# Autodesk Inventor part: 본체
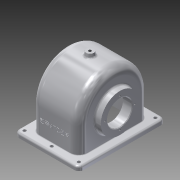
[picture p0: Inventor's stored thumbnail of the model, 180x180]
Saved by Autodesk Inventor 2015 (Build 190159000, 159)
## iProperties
Created: 2015-09
Part Number: 본체
Material: 알루미늄 6061
Document SubType Name: Modeling
Designer: PHO-1
Density: 2.7 g/cm^3
Appearance: 알루미늄 - 평지
Mass: 667.995 g
Surface Area: 883.587 cm^2
Volume: 247.405 cm^3
Author: PHO-1
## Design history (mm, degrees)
sketch "스케치2"
  geometry: L1 (-45, -70)-(45, -70); L2 (52, -63)-(52, 63); L3 (45, 70)-(-45, 70); L4 (-52, 63)-(-52, -63); L5 (-52, -70)-(52, 70); L6 (52, -70)-(-52, 70); A1 r 7 centre (-45, 63) between (-45, 70) and (-52, 63); A2 r 7 centre (45, 63) between (52, 63) and (45, 70); A3 r 7 centre (45, -63) between (45, -70) and (52, -63); A4 r 7 centre (-45, -63) between (-52, -63) and (-45, -70); 1 further point
  constraints: 12 end point, 8 point on circle, 8 point on line, 8 tangent, 4 centre point, 3 equal radius, 2 midpoint, 2 parallel, 1 horizontal, 1 perpendicular
  dimensions: "d2" = 7 radius of A1
extrude "돌출1" new body sketch "스케치2" distance "d3" = 7; taper "d4" = 0 deg
sketch "스케치3"
  geometry: L1 (44, -62)-(-44, -62); L2 (-44, -62)-(-44, 62); L3 (-44, 62)-(44, 62); L4 (44, 62)-(44, -62); 7 further points
  constraints: 8 end point, 4 coincident, 2 midpoint, 2 parallel, 1 horizontal, 1 perpendicular
  dimensions: "d5" = 88 distance of L2.end L3.end; "d6" = 124 distance of L1.end L2.end
hole "구멍1" sketch "스케치3" at (-44, 62), (0, 62), (44, 62), (44, -62), (0, -62), (-44, -62) diameter "d7" = 5; stored, may be unused: countersink angle "d11" = 90 deg, drill point angle "d13" = 0 deg; dims "d8" = 6, "d9" = 4, "d10" = 2, "d12" = 8
sketch "스케치4"
  geometry: L1 (59.5, 7)-(59.5, 0) reference; L2 (59.5, 0)-(-59.5, 0) reference; L3 (-59.5, 0)-(-59.5, 7) reference; L4 (-59.5, 7)-(59.5, 7) reference; L5 (-70, 0)-(-70, 7) reference; L6 (-70, 7)-(-64.5, 7) reference; L7 (-64.5, 7)-(-64.5, 0) reference; L8 (-64.5, 0)-(-70, 0) reference; L9 (70, 7)-(70, 0) reference; L10 (70, 0)-(64.5, 0) reference; L11 (64.5, 0)-(64.5, 7) reference; L12 (64.5, 7)-(70, 7) reference; L13 (57, 47)-(57, 7); L14 (-57, 7)-(-57, 47); A1 r 57 centre (0, 47) between (57, 47) and (-57, 47)
  constraints: 4 end point, 2 point on circle, 2 point on line, 1 centre point, 1 parallel
  dimensions: "d94" = 57 radius of A1
extrude "돌출2" join sketch "스케치4" stored distance "d19" = 77; taper "d20" = 0 deg
sketch "스케치5"
  geometry: L1 (59.5, 7)-(59.5, 0) reference; L2 (59.5, 0)-(-59.5, 0) reference; L3 (-59.5, 0)-(-59.5, 7) reference; L4 (-59.5, 7)-(-57, 7) reference; L5 (-57, 7)-(-57, 47) reference; L6 (57, 47)-(57, 7) reference; L7 (57, 7)-(59.5, 7) reference; L8 (-70, 0)-(-70, 7) reference; L9 (-70, 7)-(-64.5, 7) reference; L10 (-64.5, 7)-(-64.5, 0) reference; L11 (-64.5, 0)-(-70, 0) reference; L12 (70, 7)-(70, 0) reference; L13 (70, 0)-(64.5, 0) reference; L14 (64.5, 0)-(64.5, 7) reference; L15 (64.5, 7)-(70, 7) reference; L16 (-51, 47)-(-51, 0); L17 (51, 0)-(51, 47); A1 r 57 centre (0, 47) between (57, 47) and (-57, 47) reference; A2 r 51 centre (0, 47) between (51, 47) and (-51, 47); 1 further point
  constraints: 4 end point, 2 point on circle, 2 point on line, 1 centre point
  dimensions: "d21" = 6 radial gap between concentric circles of A1 A2
extrude "돌출3" cut sketch "스케치5" stored distance "d22" = 67; taper "d23" = 0 deg
sketch "스케치6"
  geometry: C1 r 31 at (-47, 0); 2 further points
  constraints: 1 centre point, 1 coincident
  dimensions: "d24" = 62 diameter of C1
extrude "돌출4" join sketch "스케치6" distance "d25" = 10; taper "d26" = 0 deg
node "작업 평면1"
sketch "스케치8"
  geometry: C1 r 28 at (-47, 0); 2 further points
  constraints: 1 centre point, 1 coincident
  dimensions: "d28" = 28 radius of C1
extrude "돌출5" join sketch "스케치8" stored distance "d29" = 10; taper "d30" = 40 deg
sketch "스케치10"
  geometry: L1 (38.5, 84.416)-(24.5, 72.668); L2 (24.5, 72.668)-(24.5, 47); L3 (38.5, 47)-(38.5, 84.416); L4 (38.5, 47)-(24.5, 47); 1 further point
  constraints: 8 end point, 1 point on line
revolve "회전1" sketch "스케치10" stored, may be unused: angle "d33" = 90 deg
sketch "스케치12"
  geometry: L1 (33.5, 47)-(-33.5, 47) reference; L2 (19.5, 47)-(35.5, 47); L3 (35.5, 47)-(35.5, 80); L4 (19.5, 75)-(19.5, 47); L5 (35.5, 80)-(33.237, 80); L6 (19.5, 75)-(33.237, 80); 1 further point
  constraints: 10 end point, 2 parallel, 1 horizontal, 1 perpendicular, 1 point on line
  dimensions: "d37" = 33 distance of L3.end L2.end
revolve "회전2" sketch "스케치12" stored, may be unused: angle "d38" = 90 deg
node "작업 평면4"
  node "작업 평면3"
sketch "스케치14"
  geometry: C1 r 6 at (0, 0); 1 further point
  constraints: 1 centre point, 1 coincident
  dimensions: "d40" = 6 radius of C1
extrude "돌출6" join sketch "스케치14" stored distance "d41" = 10; taper "d42" = 10 deg
sketch "스케치16"
  geometry: 2 further points
  constraints: 1 coincident
hole "구멍2" sketch "스케치16" at (0, 0) diameter "d43" = 4.459; stored, may be unused: countersink angle "d47" = 90 deg, drill point angle "d49" = 0 deg; dims "d44" = 15, "d45" = 4, "d46" = 2, "d48" = 12.8
sketch "스케치17"
  geometry: 2 further points
hole "구멍3" sketch "스케치17" at (0, 0) diameter "d50" = 40; stored, may be unused: countersink angle "d54" = 90 deg, drill point angle "d56" = 0 deg; dims "d51" = 15, "d52" = 4, "d53" = 2, "d55" = 12.8
sketch "스케치18"
  geometry: C1 r 20 at (0, 0) reference; C2 r 33 at (0, 0) reference; 5 further points
  constraints: 5 other
  dimensions: "d57" = 28 distance of C2.centre point (28, 0); "d60" = 360 deg dimension on C1.centre point (28, 0) (derived)
hole "구멍4" sketch "스케치18" at (28, 0), (0, 28), (-28, 0), (0, -28) diameter "d62" = 2.459; stored, may be unused: countersink angle "d66" = 90 deg, drill point angle "d68" = 118 deg; dims "d63" = 7, "d64" = 4, "d65" = 2, "d67" = 9
sketch "스케치19"
  geometry: C1 r 20 at (0, 0) reference; C2 r 31 at (0, 0) reference; 5 further points
  constraints: 5 other
  dimensions: "d69" = 24 distance of point (-24, 0) C1.centre; "d72" = 360 deg dimension on C1.centre point (-24, 0) (derived)
hole "구멍5" sketch "스케치19" at (-24, 0), (0, -24), (24, 0), (0, 24) diameter "d74" = 2.459; stored, may be unused: countersink angle "d78" = 90 deg, drill point angle "d80" = 118 deg; dims "d75" = 6, "d76" = 4, "d77" = 2, "d79" = 8
fillet "모깎기1" dims "d81" = 14, "d82" = 9, "d83" = 3
fillet "모깎기2" dims "d84" = 3, "d85" = 0.5, "d86" = 1
chamfer "모따기1" distance "d87" = 1; stored, may be unused: second distance "d88" = 2, angle "d89" = 45 deg
sketch "스케치20"
  geometry: L1 (-14, 0)-(-14, -39) reference; L2 (69.5, -47)-(-20.5, -47) reference; 2 further points
  constraints: 1 other
  dimensions: "d90" = 38.5 distance from line of L1 point (24.5, -17); "d91" = 30 distance from line of L2 point (24.5, -17)
feature "엠보싱1" sketch "스케치20" dims "d2" = 7, "d7" = 5, "d92" = 0.5, "d93" = 0
node "솔리드1"
node "투영된 루프4"
node "투영된 루프5"
node "절단 모서리 투영1"
node "절단 모서리 투영2"
other parameters: "d27" = 14, "d39" = 6
